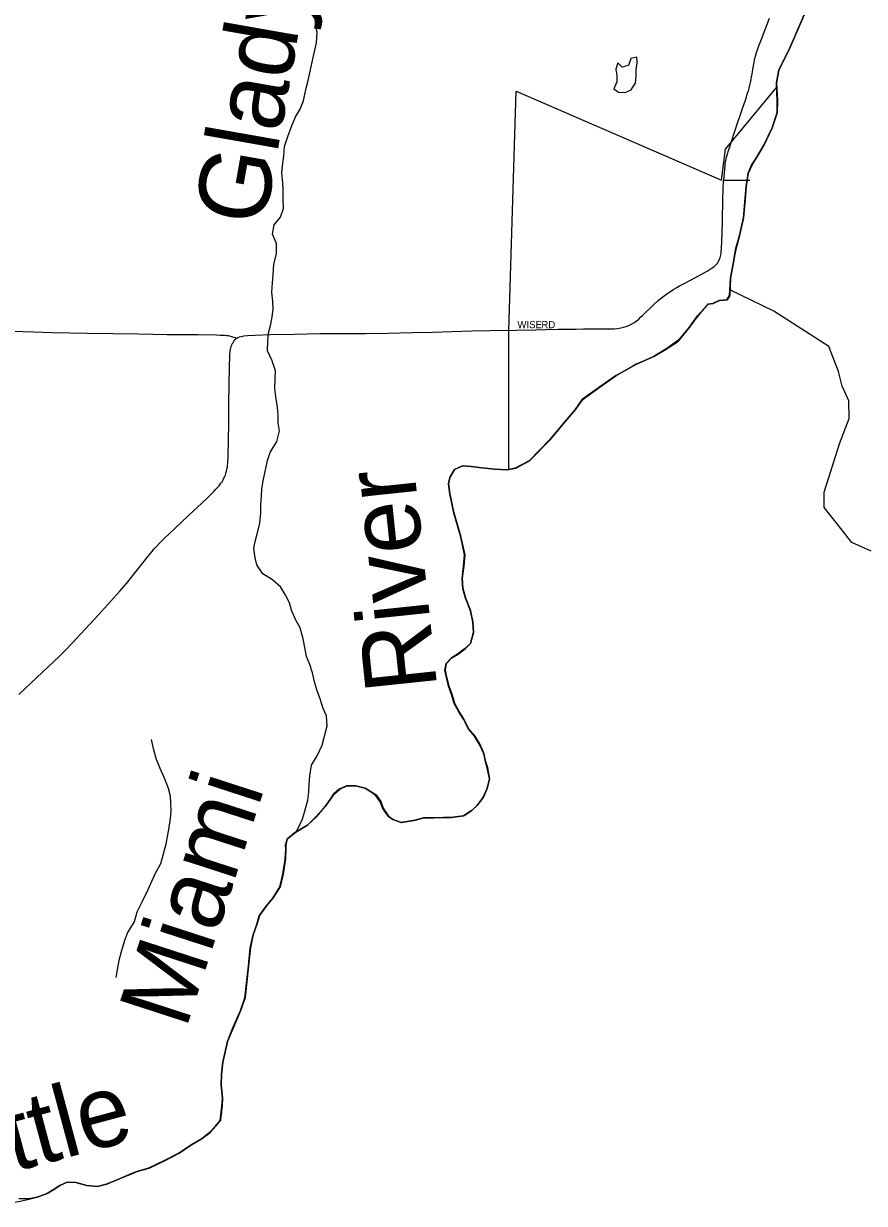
# Model space of a CAD drawing. Extents: x 1442749 to 1756758, y 235267 to 677782.
# Drawn here: x 1596586 to 1602458, y 448248 to 456494 of the extents above; entities that cross this region are included whole.
import ezdxf

# ---------------------------------------------------------------- set-up
doc = ezdxf.new("R2010")
doc.units = 0
for name, color, linetype in [('GM_X_Adjacent_County', 7, 'Continuous'), ('GM_X_City_Street', 7, 'Continuous'), ('GM_X_City_Street_Text', 7, 'Continuous'), ('GM_X_Corporation', 7, 'Continuous'), ('GM_X_County', 7, 'Continuous'), ('GM_X_County_Road', 7, 'Continuous'), ('GM_X_Major_River', 7, 'Continuous'), ('GM_X_Major_River_Text', 7, 'Continuous'), ('GM_X_Minor_Lake', 7, 'Continuous'), ('GM_X_Minor_River', 7, 'Continuous'), ('GM_X_Minor_River_Text', 7, 'Continuous'), ('GM_X_Township', 7, 'Continuous')]:
    doc.layers.add(name, color=color, linetype=linetype)

msp = doc.modelspace()

# ---------------------------------------------------------------- linework, layer by layer
at = {"layer": 'GM_X_Adjacent_County'}
msp.add_lwpolyline([(1596552.5, 448281.7), (1596622.7, 448280.3), (1596681, 448291.2), (1596749.8, 448318), (1596792.4, 448343.3), (1596839.1, 448374.4), (1596889.7, 448397.5), (1596949.8, 448394.3), (1597027.7, 448372.8), (1597101.8, 448367.3), (1597164.3, 448382.2), (1597227, 448409), (1597326, 448449.2), (1597376.6, 448470.3), (1597459.3, 448494.8), (1597566.6, 448544.8), (1597670, 448599), (1597765.5, 448663.3), (1597832.4, 448702.2), (1597885.4, 448743.3), (1597924.3, 448786.6), (1597959.2, 448828.1), (1597971.2, 448928.2), (1597974.2, 448982.3), (1597966.1, 449078.7), (1597967.4, 449148.9), (1597977.1, 449235), (1598010, 449380.8), (1598047.9, 449474.3), (1598100.4, 449595.7), (1598132.3, 449685.3), (1598156.6, 449907.5), (1598169.1, 450033.7), (1598188.9, 450125.6), (1598214.4, 450199.3), (1598231.6, 450259.1), (1598281, 450326.4), (1598326.2, 450381.7), (1598375.9, 450460.9), (1598397.7, 450548.8), (1598413.7, 450654.8), (1598417.1, 450725), (1598415.6, 450751.1), (1598426.5, 450795), (1598477.5, 450838.1), (1598568.8, 450892.5), (1598630.1, 450951.5), (1598691.7, 451022.5), (1598726.7, 451070), (1598753.5, 451109.6), (1598790.3, 451143), (1598840.9, 451166.1), (1598907.1, 451166.8), (1598971, 451149.5), (1599016.6, 451122.5), (1599044.3, 451101.9), (1599077.5, 451055.1), (1599094.6, 451008.7), (1599131.7, 450953.8), (1599165.3, 450931), (1599223.1, 450909.9), (1599319.7, 450926), (1599378.2, 450943), (1599450.4, 450943.6), (1599518.7, 450944.2), (1599568.8, 450945.3), (1599621.1, 450952.3), (1599659.3, 450957.5), (1599712.2, 450992.6), (1599753, 451029.9), (1599794.2, 451083.3), (1599823.5, 451148.9), (1599838.8, 451214.8), (1599824.3, 451291.3), (1599811, 451333.7), (1599800.1, 451390.1), (1599771.2, 451454.9), (1599736.3, 451513.7), (1599691.2, 451566.8), (1599658.3, 451633.6), (1599625.2, 451684.4), (1599594.2, 451741.2), (1599575.4, 451805.8), (1599554.4, 451862.3), (1599539.6, 451924.8), (1599528.5, 451975.2), (1599537.4, 452021.1), (1599574.3, 452060.5), (1599616.9, 452085.8), (1599665.8, 452123), (1599706.7, 452162.3), (1599728.2, 452240.1), (1599723.6, 452310.4), (1599707, 452389), (1599672.6, 452477.9), (1599653.9, 452544.5), (1599649.2, 452616.8), (1599658.9, 452700.9), (1599666.4, 452781), (1599638.7, 452903.9), (1599589.8, 453073.3), (1599562.3, 453206.3), (1599553.6, 453276.7), (1599562.6, 453322.6), (1599595.7, 453378.2), (1599650.4, 453403.2), (1599712.5, 453397.9), (1599786.5, 453388.5), (1599876.6, 453378.7), (1599960.8, 453375), (1600021.2, 453385.9), (1600116.4, 453438.2), (1600261.7, 453585.8), (1600354.1, 453696.4), (1600438.3, 453795.1), (1600489.8, 453868.3), (1600609.9, 453954.2), (1600719.7, 454032.3), (1600861.6, 454111.8), (1600987.1, 454167.5), (1601078.4, 454221.9), (1601155.7, 454274.6), (1601235.8, 454371.3), (1601293.5, 454450.4), (1601367.3, 454533.3), (1601399.4, 454536.6), (1601444, 454557.8), (1601498.2, 454562.8), (1601516.9, 454592.5), (1601523.2, 454714.8), (1601540.7, 454815.2), (1601561.4, 454924.7), (1601585.1, 455012.5), (1601613.6, 455136.3), (1601625.2, 455274), (1601631.9, 455354.6), (1601645.7, 455448.6), (1601670.9, 455504.3), (1601701.9, 455553.9), (1601755.8, 455643.1), (1601814.3, 455766.3), (1601848.5, 455872), (1601850, 455952.2), (1601844.5, 456080.7), (1601851.3, 456118.9), (1601860.2, 456168.6), (1601939.6, 456329.6), (1602265.1, 457085.6)], dxfattribs=at)
at = {"layer": 'GM_X_City_Street'}
msp.add_lwpolyline([(1600026.5, 454351.2), (1600164.2, 454354.5), (1600233.1, 454356), (1600318.5, 454357.2), (1600439.8, 454359.1), (1600495.7, 454360.1), (1600597.5, 454359.9), (1600689.3, 454360.5), (1600709.7, 454361.7), (1600731.5, 454363.1), (1600756.7, 454366.5), (1600779, 454371.6), (1600795.4, 454376.5), (1600812.5, 454383.3), (1600834.4, 454394.4), (1600851.7, 454405.1), (1600867.4, 454417.4), (1600882.2, 454429.2), (1600895.7, 454441.2), (1600908.8, 454453), (1600986.2, 454529), (1601017.9, 454557.9), (1601033, 454570.3), (1601051, 454585.1), (1601068.1, 454597.6), (1601085.7, 454610.5), (1601104.6, 454622.6), (1601127.4, 454637.2), (1601148.5, 454649.6), (1601168, 454660.1), (1601190.7, 454672.4), (1601242.9, 454700.2), (1601360.8, 454764.5), (1601388.6, 454781.3), (1601406.9, 454794.5), (1601421.1, 454807.3), (1601431.2, 454819.4), (1601439.4, 454832.9), (1601447.5, 454850), (1601453.3, 454868.2), (1601457.1, 454887), (1601458.8, 454903.9), (1601460, 454915.9), (1601462.2, 454978.1), (1601463.9, 455027.3), (1601466.3, 455112.6), (1601469.4, 455270.2), (1601474.5, 455399.4)], dxfattribs=at)
at = {"layer": 'GM_X_Corporation'}
msp.add_lwpolyline([(1602506.4, 452807.7), (1602370.9, 452866.6), (1602267.8, 452996.8), (1602177.4, 453112.6), (1602177.9, 453218.8), (1602287.7, 453564.8), (1602352.8, 453733), (1602349.2, 453857.8), (1602304, 453959.1), (1602276.9, 454062.2), (1602210, 454237.6), (1601824.8, 454483.6), (1601518.9, 454632.2), (1601516.9, 454592.5), (1601498.2, 454562.8), (1601466.7, 454559.5), (1601444, 454557.8), (1601399.6, 454536.7), (1601367.8, 454533.3), (1601330.7, 454492.9), (1601273.5, 454423.1), (1601227.1, 454360.9), (1601163.2, 454283.6), (1601079.1, 454222.4), (1600983, 454164.1), (1600864.1, 454112.6), (1600811.5, 454081.7), (1600724.6, 454034.8), (1600670.8, 453998.2), (1600491.8, 453869.7), (1600422.7, 453775.7), (1600264.6, 453589.2), (1600116.4, 453438.2), (1600020.3, 453385.7), (1599974.5, 453377.5), (1599975.1, 454346.1), (1600026.5, 456022.2), (1601461.3, 455399.6), (1601487.6, 455615.9), (1601845.9, 456048.7), (1601844.5, 456080.7), (1601860.2, 456168.6), (1601939.6, 456329.6), (1602265.1, 457085.6)], dxfattribs=at)
at = {"layer": 'GM_X_County'}
msp.add_lwpolyline([(1602265.1, 457085.6), (1601939.6, 456329.6), (1601860.2, 456168.6), (1601851.3, 456118.9), (1601844.5, 456080.7), (1601850, 455952.2), (1601848.5, 455872), (1601814.3, 455766.3), (1601755.8, 455643.1), (1601701.9, 455553.9), (1601670.9, 455504.3), (1601645.7, 455448.6), (1601631.9, 455354.6), (1601625.2, 455274), (1601613.6, 455136.3), (1601585.1, 455012.5), (1601561.4, 454924.7), (1601540.7, 454815.2), (1601523.2, 454714.8), (1601516.9, 454592.5), (1601498.2, 454562.8), (1601444, 454557.8), (1601399.4, 454536.6), (1601367.3, 454533.3), (1601293.5, 454450.4), (1601235.8, 454371.3), (1601155.7, 454274.6), (1601078.4, 454221.9), (1600987.1, 454167.5), (1600861.6, 454111.8), (1600719.7, 454032.3), (1600609.9, 453954.2), (1600489.8, 453868.3), (1600438.3, 453795.1), (1600354.1, 453696.4), (1600261.7, 453585.8), (1600116.4, 453438.2), (1600021.2, 453385.9), (1599960.8, 453375), (1599876.6, 453378.7), (1599786.5, 453388.5), (1599712.5, 453397.9), (1599650.4, 453403.2), (1599595.7, 453378.2), (1599562.6, 453322.6), (1599553.6, 453276.7), (1599562.3, 453206.3), (1599589.8, 453073.3), (1599638.7, 452903.9), (1599666.4, 452781), (1599658.9, 452700.9), (1599649.2, 452616.8), (1599653.9, 452544.5), (1599672.6, 452477.9), (1599707, 452389), (1599723.6, 452310.4), (1599728.2, 452240.1), (1599706.7, 452162.3), (1599665.8, 452123), (1599616.9, 452085.8), (1599574.3, 452060.5), (1599537.4, 452021.1), (1599528.5, 451975.2), (1599539.6, 451924.8), (1599554.4, 451862.3), (1599575.4, 451805.8), (1599594.2, 451741.2), (1599625.2, 451684.4), (1599658.3, 451633.6), (1599691.2, 451566.8), (1599736.3, 451513.7), (1599771.2, 451454.9), (1599800.1, 451390.1), (1599811, 451333.7), (1599824.3, 451291.3), (1599838.8, 451214.8), (1599823.5, 451148.9), (1599794.2, 451083.3), (1599753, 451029.9), (1599712.2, 450992.6), (1599659.3, 450957.5), (1599621.1, 450952.3), (1599568.8, 450945.3), (1599518.7, 450944.2), (1599450.4, 450943.6), (1599378.2, 450943), (1599319.7, 450926), (1599223.1, 450909.9), (1599165.3, 450931), (1599131.7, 450953.8), (1599094.6, 451008.7), (1599077.5, 451055.1), (1599044.3, 451101.9), (1599016.6, 451122.5), (1598971, 451149.5), (1598907.1, 451166.8), (1598840.9, 451166.1), (1598790.3, 451143), (1598753.5, 451109.6), (1598726.7, 451070), (1598691.7, 451022.5), (1598630.1, 450951.5), (1598568.8, 450892.5), (1598477.5, 450838.1), (1598426.5, 450795), (1598415.6, 450751.1), (1598417.1, 450725), (1598413.7, 450654.8), (1598397.7, 450548.8), (1598375.9, 450460.9), (1598326.2, 450381.7), (1598281, 450326.4), (1598231.6, 450259.1), (1598214.4, 450199.3), (1598188.9, 450125.6), (1598169.1, 450033.7), (1598156.6, 449907.5), (1598132.3, 449685.3), (1598100.4, 449595.7), (1598047.9, 449474.3), (1598010, 449380.8), (1597977.1, 449235), (1597967.4, 449148.9), (1597966.1, 449078.7), (1597974.2, 448982.3), (1597971.2, 448928.2), (1597959.2, 448828.1), (1597924.3, 448786.6), (1597885.4, 448743.3), (1597832.4, 448702.2), (1597765.5, 448663.3), (1597670, 448599), (1597566.6, 448544.8), (1597459.3, 448494.8), (1597376.6, 448470.3), (1597326, 448449.2), (1597227, 448409), (1597164.3, 448382.2), (1597101.8, 448367.3), (1597027.7, 448372.8), (1596949.8, 448394.3), (1596889.7, 448397.5), (1596839.1, 448374.4), (1596792.4, 448343.3), (1596749.8, 448318), (1596681, 448291.2), (1596622.7, 448280.3), (1596552.5, 448281.7)], dxfattribs=at)
at = {"layer": 'GM_X_County_Road'}
for points in [[(1601793.9, 456529.6), (1601736.2, 456383), (1601719.5, 456337.1), (1601709, 456308.2), (1601702.5, 456290.2), (1601694.6, 456265), (1601689.5, 456240.8), (1601685.7, 456223), (1601681.8, 456200.8), (1601676.7, 456171.4), (1601671.7, 456142.9), (1601668.1, 456122.7), (1601664.3, 456104), (1601659.8, 456081.1), (1601655.1, 456062.6), (1601650.3, 456043.2), (1601645.5, 456024.1), (1601640.1, 456006), (1601627.8, 455964.5), (1601602.7, 455890.1), (1601555.9, 455753.5), (1601520.6, 455647.5), (1601515.2, 455629.4), (1601507.5, 455604.1), (1601500.5, 455580.8), (1601495.9, 455565.7), (1601491.1, 455551.3), (1601487.2, 455534.9), (1601483.7, 455517.8), (1601482.5, 455503), (1601476.4, 455425.2)], [(1601476.4, 455425.2), (1601474.5, 455399.4)], [(1601474.5, 455399.4), (1601564.3, 455399.5), (1601657.6, 455400.1)], [(1596428.3, 454346), (1596654.5, 454339.8), (1596788.8, 454335.9), (1597031.5, 454330.6), (1597389, 454325.2), (1597589, 454321.4), (1597743.1, 454321.3), (1597802.1, 454320.4), (1597933.2, 454317.8), (1597958.1, 454317.1), (1597982.4, 454316.3), (1597992.1, 454316.1), (1598002.6, 454315.1), (1598014.2, 454313.3), (1598030.6, 454308.4), (1598075.2, 454295.1)], [(1598075.2, 454295.1), (1598081.7, 454299.3), (1598092.9, 454304.2), (1598106.3, 454308), (1598124.1, 454311.2), (1598150.8, 454313.9), (1598203.5, 454317.4), (1598308.5, 454321), (1598479.1, 454324.4), (1598656, 454327.2), (1598790, 454327.5), (1598973.5, 454328.7), (1599130.7, 454331), (1599304.4, 454335.4), (1599442.1, 454338.4), (1599717.6, 454347.3), (1599842.3, 454349.5), (1600026.5, 454351.2)], [(1596551.7, 451805.7), (1596635.9, 451883.7), (1596836, 452072.9), (1596877.8, 452114.5), (1596923.1, 452161.9), (1597108, 452361.7), (1597255.5, 452524.6), (1597304.6, 452581.6), (1597349.9, 452637.6), (1597457.5, 452774.3), (1597480.6, 452801.6), (1597497.9, 452822), (1597514.8, 452840.3), (1597533.6, 452860.7), (1597554, 452880.8), (1597573.3, 452899.9), (1597600.4, 452925.5), (1597735.6, 453053.1), (1597862.5, 453172), (1597916, 453224.9), (1597927.4, 453237), (1597940.6, 453251), (1597948.8, 453260.9), (1597957.2, 453270.9), (1597964.7, 453281.7), (1597972, 453292), (1597977, 453300.6), (1597983.3, 453311.4), (1597989.1, 453324.2), (1597995.1, 453337.8), (1597999.5, 453351.9), (1598003.7, 453365.5), (1598006.6, 453380.9), (1598009.2, 453394), (1598010.7, 453407), (1598012.5, 453422.9), (1598013.3, 453438.9), (1598014.1, 453453.3), (1598014.9, 453468.6), (1598017.7, 453580), (1598018.4, 453701.4), (1598020.2, 453826), (1598021.3, 453980.2), (1598027.1, 454180.4), (1598029.1, 454203.6), (1598031.3, 454215.2), (1598033.4, 454226.7), (1598036.5, 454236.5), (1598039.5, 454246.1), (1598042.9, 454254.8), (1598046.6, 454261.5), (1598054.1, 454273.7), (1598061.8, 454283.5), (1598070.2, 454291.9), (1598075.2, 454295.1)]]:
    msp.add_lwpolyline(points, dxfattribs=at)
at = {"layer": 'GM_X_Major_River'}
for points in [[(1599756.2, 451030.8), (1599797.4, 451084.2), (1599826.7, 451149.8), (1599842, 451215.7), (1599827.4, 451292.2), (1599814.2, 451334.6), (1599803.3, 451391), (1599774.4, 451455.8), (1599739.5, 451514.6), (1599694.4, 451567.7), (1599661.5, 451634.5), (1599628.8, 451685.1), (1599597.4, 451742.1), (1599578.6, 451806.7), (1599557.6, 451863.2), (1599542.8, 451925.7), (1599531.7, 451976.1), (1599540.6, 452022), (1599577.5, 452061.5), (1599620.1, 452086.7), (1599669, 452123.9), (1599709.9, 452163.2), (1599731.4, 452241), (1599726.8, 452311.3), (1599710.2, 452389.9), (1599675.8, 452478.8), (1599657.1, 452545.4), (1599652.4, 452617.7), (1599662.1, 452701.8), (1599669.6, 452781.9), (1599641.9, 452904.8), (1599593, 453074.2), (1599565.5, 453207.2), (1599556.8, 453277.6), (1599565.7, 453323.5), (1599598.9, 453379.1), (1599653.6, 453404.1), (1599715.6, 453398.8), (1599789.7, 453389.4), (1599879.8, 453379.6), (1599964, 453376), (1600024.4, 453386.8), (1600119.6, 453439.1), (1600264.9, 453586.8), (1600357.3, 453697.3), (1600441.5, 453796), (1600493, 453869.2), (1600613.1, 453955.1), (1600722.9, 454033.2), (1600864.8, 454112.7), (1600990.3, 454168.4), (1601081.6, 454222.8), (1601158.9, 454275.5), (1601239, 454372.2), (1601296.7, 454451.3), (1601370.5, 454534.2), (1601402.6, 454537.5), (1601447.2, 454558.7), (1601501.4, 454563.7), (1601520.1, 454593.4), (1601526.4, 454715.7), (1601544.5, 454819.6), (1601564.6, 454925.6), (1601588.3, 455013.4), (1601616.8, 455137.2), (1601627.2, 455261.4), (1601635.1, 455355.5), (1601648.9, 455449.5), (1601674.1, 455505.2), (1601705.1, 455554.8), (1601759, 455644), (1601817.5, 455767.2), (1601851.7, 455872.9), (1601853.2, 455953.1), (1601847.7, 456081.6), (1601863.4, 456169.6), (1601942.8, 456330.5), (1602268.3, 457086.5)], [(1596684.2, 448292.1), (1596753, 448318.9), (1596795.6, 448344.1), (1596842.3, 448375.3), (1596892.9, 448398.4), (1596953, 448395.2), (1597030.8, 448373.7), (1597105, 448368.2), (1597167.4, 448383), (1597230.2, 448409.9), (1597329.2, 448450.1), (1597379.8, 448471.2), (1597462.5, 448495.7), (1597569.8, 448545.7), (1597673.1, 448599.9), (1597768.7, 448664.2), (1597835.6, 448703.1), (1597888.6, 448744.1), (1597927.5, 448787.5), (1597962.4, 448829), (1597974.4, 448929), (1597977.4, 448983.1), (1597969.3, 449079.6), (1597970.6, 449149.8), (1597980.3, 449235.9), (1598013.2, 449381.7), (1598051.1, 449475.2), (1598103.6, 449596.6), (1598135.4, 449686.2), (1598159.8, 449908.4), (1598172.3, 450034.6), (1598192.1, 450126.5), (1598217.6, 450200.2), (1598234.8, 450260), (1598284.2, 450327.3), (1598329.4, 450382.6), (1598379.1, 450461.8), (1598400.9, 450549.7), (1598416.9, 450655.7), (1598420.3, 450725.9), (1598418.8, 450752), (1598429.7, 450795.9), (1598480.7, 450839), (1598572, 450893.4), (1598633.3, 450952.4), (1598694.9, 451023.4), (1598729.9, 451070.9), (1598756.7, 451110.5), (1598793.5, 451143.9), (1598844.1, 451167), (1598910.3, 451167.7), (1598974.1, 451150.4), (1599019.8, 451123.4), (1599047.5, 451102.8), (1599080.7, 451056), (1599097.8, 451009.6), (1599134.9, 450954.7), (1599168.5, 450932), (1599226.3, 450910.8), (1599322.9, 450926.9), (1599381.4, 450943.9), (1599453.6, 450944.5), (1599521.9, 450945.1), (1599572, 450946.2), (1599624.3, 450953.2), (1599662.5, 450958.4), (1599715.4, 450993.5), (1599756.2, 451030.8)], [(1596684.2, 448292.1), (1596623, 448275.2), (1596572.6, 448263.4), (1596522.2, 448254.8), (1596488, 448248.3)]]:
    msp.add_lwpolyline(points, dxfattribs=at)
at = {"layer": 'GM_X_Minor_Lake'}
for points in [[(1600840.5, 456050.6), (1600860, 456077.1), (1600864.5, 456123.2), (1600865, 456171.3), (1600871.5, 456219.3), (1600869.9, 456259.4), (1600827.7, 456249.8), (1600811.2, 456201.9), (1600799.7, 456198.4)], [(1600799.7, 456198.4), (1600766.9, 456188.3), (1600737.2, 456220.7), (1600722.7, 456174.7), (1600730.3, 456130.6), (1600729.8, 456086.5), (1600709.3, 456038.6), (1600741.1, 456014.2), (1600787.2, 456011.7), (1600829.4, 456031.3), (1600840.5, 456050.6)]]:
    msp.add_lwpolyline(points, dxfattribs=at)
at = {"layer": 'GM_X_Minor_River'}
for points in [[(1598490.9, 450849.8), (1598530.8, 450927.4), (1598553.5, 450999.3), (1598570.3, 451067.3), (1598578.8, 451121.4), (1598579.4, 451175.5), (1598586, 451237.5), (1598596.8, 451311.6), (1598635.6, 451377.3), (1598670.4, 451451.2), (1598705.8, 451587.1), (1598702.5, 451655.3), (1598679, 451707.6), (1598657.7, 451774), (1598638.1, 451824.3), (1598616.8, 451894.6), (1598603.4, 451956.9), (1598586, 452015.2), (1598562.5, 452069.6), (1598551.1, 452133.8), (1598537.7, 452194.1), (1598516.5, 452270.5), (1598485, 452328.9), (1598457.6, 452393.3), (1598442.1, 452445.6), (1598412.6, 452504), (1598381.1, 452556.5), (1598325.5, 452607.1), (1598257.8, 452647.9), (1598214.4, 452710.5), (1598202.9, 452760.7), (1598193.5, 452826.9), (1598206.1, 452882.9), (1598218.7, 452934.9), (1598235.4, 453002.9), (1598242.1, 453073), (1598242.7, 453129.1), (1598247.3, 453191.2), (1598249.9, 453241.3), (1598260.6, 453309.3), (1598277.4, 453385.3), (1598290, 453441.3), (1598308.6, 453495.2), (1598355.5, 453572.9), (1598374.3, 453646.9), (1598364.8, 453703.1), (1598363.4, 453757.2), (1598359.9, 453813.4), (1598348.7, 453885.7), (1598341.2, 453945.9), (1598341.9, 454014), (1598344.5, 454068.1), (1598321.2, 454136.5), (1598289.8, 454206.9), (1598292.5, 454275.1), (1598297.1, 454331.1), (1598311.8, 454393.1), (1598322.3, 454445.1), (1598328.9, 454497.2), (1598327.4, 454551.3), (1598320.1, 454617.5), (1598324.7, 454681.6), (1598329.3, 454735.7), (1598334.1, 454811.8), (1598352.9, 454883.8), (1598351.6, 454956), (1598324.2, 455022.4), (1598334.9, 455088.4), (1598379.5, 455140.1), (1598402.2, 455202), (1598398.9, 455272.2), (1598399.6, 455334.3), (1598396.1, 455384.4), (1598390.7, 455448.6), (1598395.3, 455500.7), (1598404, 455570.8), (1598408.7, 455634.8), (1598431.4, 455704.8), (1598456.2, 455774.7), (1598484.9, 455842.5), (1598517.5, 455896.3), (1598540.2, 455954.2), (1598557, 456032.2), (1598573.7, 456096.2), (1598596.8, 456202.2), (1598613.6, 456278.2), (1598632.5, 456360.2), (1598635.3, 456432.3), (1598627.8, 456482.5), (1598622.3, 456532.6)], [(1597476.4, 451491.2), (1597489.8, 451427), (1597511.1, 451352.6), (1597538.5, 451290.2), (1597567.9, 451221.7), (1597595.2, 451151.3), (1597608.7, 451097.1), (1597612.1, 451042.9), (1597613.6, 450990.8), (1597609.1, 450938.7), (1597600.4, 450874.7), (1597591.9, 450824.6), (1597579.2, 450758.6), (1597560.4, 450688.7), (1597541.7, 450620.7), (1597504.9, 450554.9), (1597482.4, 450503), (1597453.6, 450439.2), (1597414.7, 450359.4), (1597375.9, 450283.6), (1597357.2, 450215.7), (1597312.3, 450142), (1597291.7, 450086.1), (1597266.8, 450006.1), (1597250.2, 449946.2), (1597241.6, 449894.1), (1597231, 449828.1)]]:
    msp.add_lwpolyline(points, dxfattribs=at)
at = {"layer": 'GM_X_Township'}
msp.add_lwpolyline([(1602265.1, 457085.6), (1601939.6, 456329.6), (1601860.2, 456168.6), (1601851.3, 456118.9), (1601844.5, 456080.7), (1601850, 455952.2), (1601848.5, 455872), (1601814.3, 455766.3), (1601755.8, 455643.1), (1601701.9, 455553.9), (1601670.9, 455504.3), (1601645.7, 455448.6), (1601631.9, 455354.6), (1601625.2, 455274), (1601613.6, 455136.3), (1601585.1, 455012.5), (1601561.4, 454924.7), (1601540.7, 454815.2), (1601523.2, 454714.8), (1601516.9, 454592.5), (1601498.2, 454562.8), (1601444, 454557.8), (1601399.4, 454536.6), (1601367.3, 454533.3), (1601293.5, 454450.4), (1601235.8, 454371.3), (1601155.7, 454274.6), (1601078.4, 454221.9), (1600987.1, 454167.5), (1600861.6, 454111.8), (1600719.7, 454032.3), (1600609.9, 453954.2), (1600489.8, 453868.3), (1600438.3, 453795.1), (1600354.1, 453696.4), (1600261.7, 453585.8), (1600116.4, 453438.2), (1600021.2, 453385.9), (1599960.8, 453375), (1599876.6, 453378.7), (1599786.5, 453388.5), (1599712.5, 453397.9), (1599650.4, 453403.2), (1599595.7, 453378.2), (1599562.6, 453322.6), (1599553.6, 453276.7), (1599562.3, 453206.3), (1599589.8, 453073.3), (1599638.7, 452903.9), (1599666.4, 452781), (1599658.9, 452700.9), (1599649.2, 452616.8), (1599653.9, 452544.5), (1599672.6, 452477.9), (1599707, 452389), (1599723.6, 452310.4), (1599728.2, 452240.1), (1599706.7, 452162.3), (1599665.8, 452123), (1599616.9, 452085.8), (1599574.3, 452060.5), (1599537.4, 452021.1), (1599528.5, 451975.2), (1599539.6, 451924.8), (1599554.4, 451862.3), (1599575.4, 451805.8), (1599594.2, 451741.2), (1599625.2, 451684.4), (1599658.3, 451633.6), (1599691.2, 451566.8), (1599736.3, 451513.7), (1599771.2, 451454.9), (1599800.1, 451390.1), (1599811, 451333.7), (1599824.3, 451291.3), (1599838.8, 451214.8), (1599823.5, 451148.9), (1599794.2, 451083.3), (1599753, 451029.9), (1599712.2, 450992.6), (1599659.3, 450957.5), (1599621.1, 450952.3), (1599568.8, 450945.3), (1599518.7, 450944.2), (1599450.4, 450943.6), (1599378.2, 450943), (1599319.7, 450926), (1599223.1, 450909.9), (1599165.3, 450931), (1599131.7, 450953.8), (1599094.6, 451008.7), (1599077.5, 451055.1), (1599044.3, 451101.9), (1599016.6, 451122.5), (1598971, 451149.5), (1598907.1, 451166.8), (1598840.9, 451166.1), (1598790.3, 451143), (1598753.5, 451109.6), (1598726.7, 451070), (1598691.7, 451022.5), (1598630.1, 450951.5), (1598568.8, 450892.5), (1598477.5, 450838.1), (1598426.5, 450795), (1598415.6, 450751.1), (1598417.1, 450725), (1598413.7, 450654.8), (1598397.7, 450548.8), (1598375.9, 450460.9), (1598326.2, 450381.7), (1598281, 450326.4), (1598231.6, 450259.1), (1598214.4, 450199.3), (1598188.9, 450125.6), (1598169.1, 450033.7), (1598156.6, 449907.5), (1598132.3, 449685.3), (1598100.4, 449595.7), (1598047.9, 449474.3), (1598010, 449380.8), (1597977.1, 449235), (1597967.4, 449148.9), (1597966.1, 449078.7), (1597974.2, 448982.3), (1597971.2, 448928.2), (1597959.2, 448828.1), (1597924.3, 448786.6), (1597885.4, 448743.3), (1597832.4, 448702.2), (1597765.5, 448663.3), (1597670, 448599), (1597566.6, 448544.8), (1597459.3, 448494.8), (1597376.6, 448470.3), (1597326, 448449.2), (1597227, 448409), (1597164.3, 448382.2), (1597101.8, 448367.3), (1597027.7, 448372.8), (1596949.8, 448394.3), (1596889.7, 448397.5), (1596839.1, 448374.4), (1596792.4, 448343.3), (1596749.8, 448318), (1596681, 448291.2), (1596622.7, 448280.3), (1596552.5, 448281.7)], dxfattribs=at)

# ---------------------------------------------------------------- texts
at = {"layer": 'GM_X_City_Street_Text'}
for s, p in [('WISE', (1600035.1, 454365.1)), ('RD', (1600202.3, 454365.1))]:
    msp.add_text(s, height=50, rotation=0.00001, dxfattribs=at).set_placement(p)
at = {"layer": 'GM_X_Major_River_Text'}
for s, height, rotation, p in [('River', 500.03, 95.99686, (1599475.8, 451851)), ('Miami', 500.03, 71.998, (1597719.3, 449458.6)), ('Little', 500.02, 15.00103, (1596011.7, 448332.2))]:
    msp.add_text(s, height=height, rotation=rotation, dxfattribs=at).set_placement(p)
at = {"layer": 'GM_X_Minor_River_Text'}
msp.add_text('Glady', height=500.04, rotation=79.99722, dxfattribs=at).set_placement((1598266, 455065.9))

doc.saveas('drawing.dxf')
